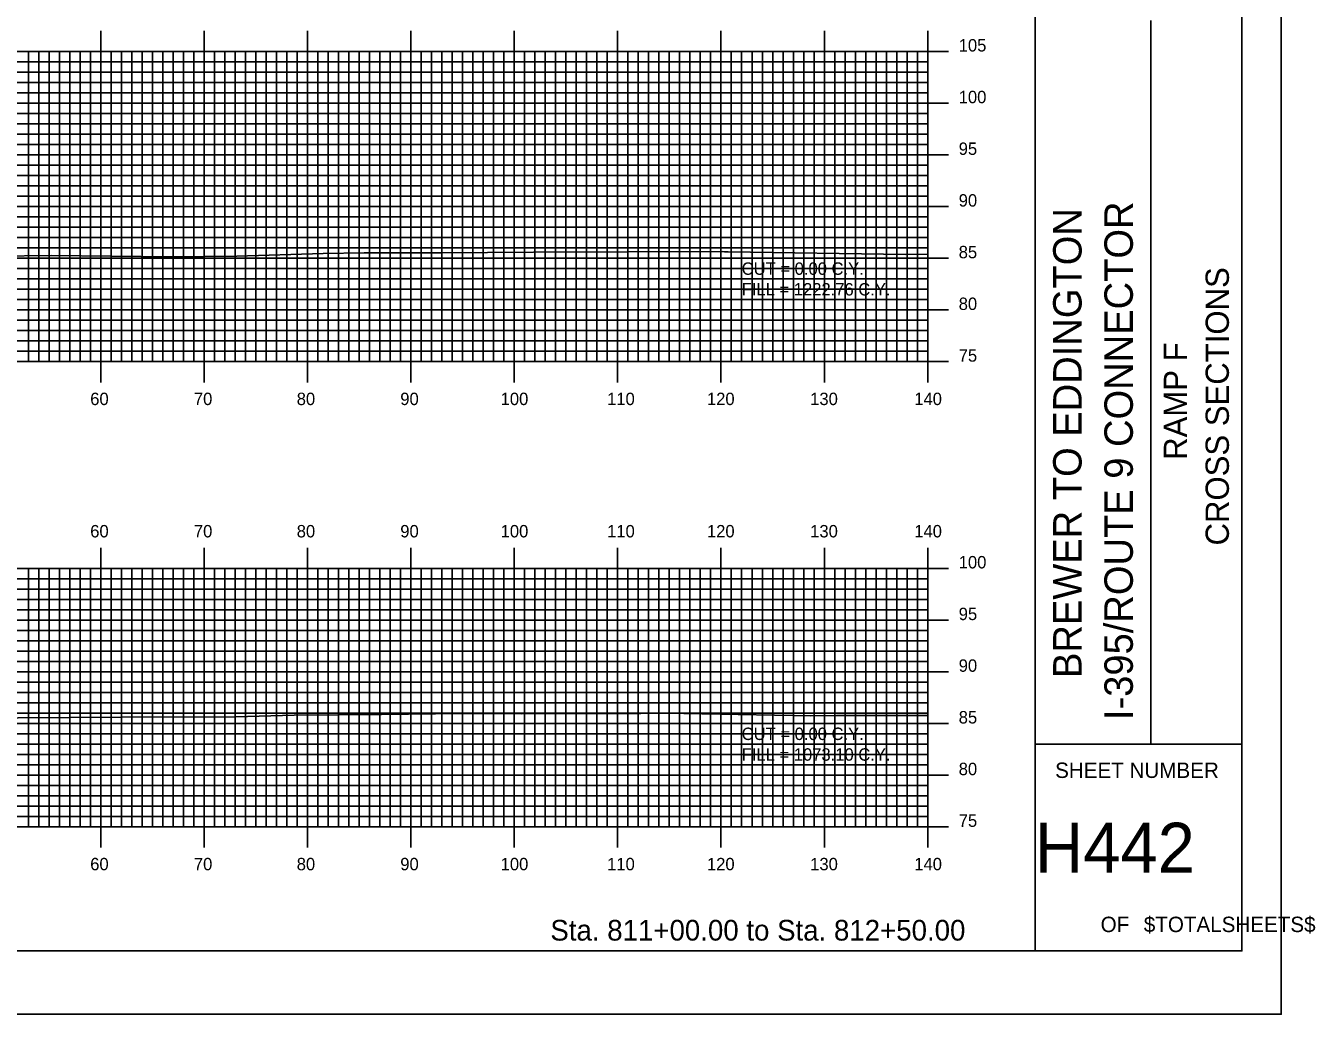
# Model space of a CAD drawing. Extents: x 2059 to 2403, y -1658 to -1438.
# Drawn here: x 2277.9 to 2402.7, y -1657.7 to -1562.1 of the extents above; entities that cross this region are included whole.
import ezdxf

# ---------------------------------------------------------------- set-up
doc = ezdxf.new("R2010")
doc.units = 0
for name, color, linetype in [('BORDER', 7, 'Continuous'), ('D_Text_Standard', 7, 'Continuous'), ('H_V ANNOTATION', 7, 'Continuous'), ('MAJOR', 7, 'Continuous'), ('MINOR', 7, 'Continuous'), ('PLOT BOUNDARY', 7, 'Continuous'), ('S_Roadway_Centerline', 7, 'Continuous')]:
    doc.layers.add(name, color=color, linetype=linetype)

msp = doc.modelspace()

# ---------------------------------------------------------------- linework, layer by layer
at = {"layer": 'BORDER'}
for p, q in [((2375.59, -1651.6), (2375.59, -1441.6)), ((2386.77, -1631.6), (2386.77, -1561.6)), ((2375.59, -1631.6), (2395.59, -1631.6))]:
    msp.add_line(p, q, dxfattribs=at)
msp.add_lwpolyline([(2075.59, -1651.6), (2395.59, -1651.6), (2395.59, -1441.6), (2075.59, -1441.6)], close=True, dxfattribs=at)
at = {"layer": 'MAJOR'}
for p, q in [((2285.19, -1562.6), (2285.19, -1564.6)), ((2295.19, -1562.6), (2295.19, -1564.6)), ((2305.19, -1562.6), (2305.19, -1564.6)), ((2315.19, -1562.6), (2315.19, -1564.6)), ((2325.19, -1562.6), (2325.19, -1564.6)), ((2335.19, -1562.6), (2335.19, -1564.6)), ((2345.19, -1562.6), (2345.19, -1564.6)), ((2355.19, -1562.6), (2355.19, -1564.6)), ((2365.19, -1562.6), (2365.19, -1564.6)), ((2085.19, -1564.6), (2365.19, -1564.6)), ((2085.19, -1564.6), (2365.19, -1564.6)), ((2285.19, -1594.6), (2285.19, -1564.6)), ((2295.19, -1594.6), (2295.19, -1564.6)), ((2305.19, -1594.6), (2305.19, -1564.6)), ((2315.19, -1594.6), (2315.19, -1564.6)), ((2325.19, -1594.6), (2325.19, -1564.6)), ((2335.19, -1594.6), (2335.19, -1564.6)), ((2345.19, -1594.6), (2345.19, -1564.6)), ((2355.19, -1594.6), (2355.19, -1564.6)), ((2367.19, -1564.6), (2363.18, -1564.6)), ((2365.19, -1594.6), (2365.19, -1564.6)), ((2365.19, -1594.6), (2365.19, -1564.6)), ((2085.19, -1569.6), (2365.19, -1569.6)), ((2367.19, -1569.6), (2363.18, -1569.6)), ((2085.19, -1574.6), (2365.19, -1574.6)), ((2367.19, -1574.6), (2363.18, -1574.6)), ((2085.19, -1579.6), (2365.19, -1579.6)), ((2367.19, -1579.6), (2363.18, -1579.6)), ((2085.19, -1584.6), (2365.19, -1584.6)), ((2367.19, -1584.6), (2363.18, -1584.6)), ((2085.19, -1589.6), (2365.19, -1589.6)), ((2367.19, -1589.6), (2363.18, -1589.6)), ((2085.19, -1594.6), (2365.19, -1594.6)), ((2085.19, -1594.6), (2365.19, -1594.6)), ((2285.19, -1596.61), (2285.19, -1594.6)), ((2295.19, -1596.61), (2295.19, -1594.6)), ((2305.19, -1596.61), (2305.19, -1594.6)), ((2315.19, -1596.61), (2315.19, -1594.6)), ((2325.19, -1596.61), (2325.19, -1594.6)), ((2335.19, -1596.61), (2335.19, -1594.6)), ((2345.19, -1596.61), (2345.19, -1594.6)), ((2355.19, -1596.61), (2355.19, -1594.6)), ((2367.19, -1594.6), (2363.18, -1594.6)), ((2365.19, -1596.61), (2365.19, -1594.6)), ((2285.19, -1612.6), (2285.19, -1614.6)), ((2295.19, -1612.6), (2295.19, -1614.6)), ((2305.19, -1612.6), (2305.19, -1614.6)), ((2315.19, -1612.6), (2315.19, -1614.6)), ((2325.19, -1612.6), (2325.19, -1614.6)), ((2335.19, -1612.6), (2335.19, -1614.6)), ((2345.19, -1612.6), (2345.19, -1614.6)), ((2355.19, -1612.6), (2355.19, -1614.6)), ((2365.19, -1612.6), (2365.19, -1614.6)), ((2085.19, -1614.6), (2365.19, -1614.6)), ((2085.19, -1614.6), (2365.19, -1614.6)), ((2285.19, -1639.6), (2285.19, -1614.6)), ((2295.19, -1639.6), (2295.19, -1614.6)), ((2305.19, -1639.6), (2305.19, -1614.6)), ((2315.19, -1639.6), (2315.19, -1614.6)), ((2325.19, -1639.6), (2325.19, -1614.6)), ((2335.19, -1639.6), (2335.19, -1614.6)), ((2345.19, -1639.6), (2345.19, -1614.6)), ((2355.19, -1639.6), (2355.19, -1614.6)), ((2367.19, -1614.6), (2363.18, -1614.6)), ((2365.19, -1639.6), (2365.19, -1614.6)), ((2365.19, -1639.6), (2365.19, -1614.6)), ((2085.19, -1619.6), (2365.19, -1619.6)), ((2367.19, -1619.6), (2363.18, -1619.6)), ((2085.19, -1624.6), (2365.19, -1624.6)), ((2367.19, -1624.6), (2363.18, -1624.6)), ((2085.19, -1629.6), (2365.19, -1629.6)), ((2367.19, -1629.6), (2363.18, -1629.6)), ((2085.19, -1634.6), (2365.19, -1634.6)), ((2367.19, -1634.6), (2363.18, -1634.6)), ((2085.19, -1639.6), (2365.19, -1639.6)), ((2085.19, -1639.6), (2365.19, -1639.6)), ((2285.19, -1641.61), (2285.19, -1639.6)), ((2295.19, -1641.61), (2295.19, -1639.6)), ((2305.19, -1641.61), (2305.19, -1639.6)), ((2315.19, -1641.61), (2315.19, -1639.6)), ((2325.19, -1641.61), (2325.19, -1639.6)), ((2335.19, -1641.61), (2335.19, -1639.6)), ((2345.19, -1641.61), (2345.19, -1639.6)), ((2355.19, -1641.61), (2355.19, -1639.6)), ((2367.19, -1639.6), (2363.18, -1639.6)), ((2365.19, -1641.61), (2365.19, -1639.6))]:
    msp.add_line(p, q, dxfattribs=at)
at = {"layer": 'MINOR'}
for p, q in [((2085.19, -1565.6), (2365.19, -1565.6)), ((2278.19, -1594.6), (2278.19, -1564.6)), ((2279.19, -1594.6), (2279.19, -1564.6)), ((2280.19, -1594.6), (2280.19, -1564.6)), ((2281.19, -1594.6), (2281.19, -1564.6)), ((2282.19, -1594.6), (2282.19, -1564.6)), ((2283.19, -1594.6), (2283.19, -1564.6)), ((2284.19, -1594.6), (2284.19, -1564.6)), ((2286.19, -1594.6), (2286.19, -1564.6)), ((2287.19, -1594.6), (2287.19, -1564.6)), ((2288.19, -1594.6), (2288.19, -1564.6)), ((2289.19, -1594.6), (2289.19, -1564.6)), ((2290.19, -1594.6), (2290.19, -1564.6)), ((2291.19, -1594.6), (2291.19, -1564.6)), ((2292.19, -1594.6), (2292.19, -1564.6)), ((2293.19, -1594.6), (2293.19, -1564.6)), ((2294.19, -1594.6), (2294.19, -1564.6)), ((2296.19, -1594.6), (2296.19, -1564.6)), ((2297.19, -1594.6), (2297.19, -1564.6)), ((2298.19, -1594.6), (2298.19, -1564.6)), ((2299.19, -1594.6), (2299.19, -1564.6)), ((2300.19, -1594.6), (2300.19, -1564.6)), ((2301.19, -1594.6), (2301.19, -1564.6)), ((2302.19, -1594.6), (2302.19, -1564.6)), ((2303.19, -1594.6), (2303.19, -1564.6)), ((2304.19, -1594.6), (2304.19, -1564.6)), ((2306.19, -1594.6), (2306.19, -1564.6)), ((2307.19, -1594.6), (2307.19, -1564.6)), ((2308.19, -1594.6), (2308.19, -1564.6)), ((2309.19, -1594.6), (2309.19, -1564.6)), ((2310.19, -1594.6), (2310.19, -1564.6)), ((2311.19, -1594.6), (2311.19, -1564.6)), ((2312.19, -1594.6), (2312.19, -1564.6)), ((2313.19, -1594.6), (2313.19, -1564.6)), ((2314.19, -1594.6), (2314.19, -1564.6)), ((2316.19, -1594.6), (2316.19, -1564.6)), ((2317.19, -1594.6), (2317.19, -1564.6)), ((2318.19, -1594.6), (2318.19, -1564.6)), ((2319.19, -1594.6), (2319.19, -1564.6)), ((2320.19, -1594.6), (2320.19, -1564.6)), ((2321.19, -1594.6), (2321.19, -1564.6)), ((2322.19, -1594.6), (2322.19, -1564.6)), ((2323.19, -1594.6), (2323.19, -1564.6)), ((2324.19, -1594.6), (2324.19, -1564.6)), ((2326.19, -1594.6), (2326.19, -1564.6)), ((2327.19, -1594.6), (2327.19, -1564.6)), ((2328.19, -1594.6), (2328.19, -1564.6)), ((2329.19, -1594.6), (2329.19, -1564.6)), ((2330.19, -1594.6), (2330.19, -1564.6)), ((2331.19, -1594.6), (2331.19, -1564.6)), ((2332.19, -1594.6), (2332.19, -1564.6)), ((2333.19, -1594.6), (2333.19, -1564.6)), ((2334.19, -1594.6), (2334.19, -1564.6)), ((2336.19, -1594.6), (2336.19, -1564.6)), ((2337.19, -1594.6), (2337.19, -1564.6)), ((2338.19, -1594.6), (2338.19, -1564.6)), ((2339.19, -1594.6), (2339.19, -1564.6)), ((2340.19, -1594.6), (2340.19, -1564.6)), ((2341.19, -1594.6), (2341.19, -1564.6)), ((2342.19, -1594.6), (2342.19, -1564.6)), ((2343.19, -1594.6), (2343.19, -1564.6)), ((2344.19, -1594.6), (2344.19, -1564.6)), ((2346.19, -1594.6), (2346.19, -1564.6)), ((2347.19, -1594.6), (2347.19, -1564.6)), ((2348.19, -1594.6), (2348.19, -1564.6)), ((2349.19, -1594.6), (2349.19, -1564.6)), ((2350.19, -1594.6), (2350.19, -1564.6)), ((2351.19, -1594.6), (2351.19, -1564.6)), ((2352.19, -1594.6), (2352.19, -1564.6)), ((2353.19, -1594.6), (2353.19, -1564.6)), ((2354.19, -1594.6), (2354.19, -1564.6)), ((2356.19, -1594.6), (2356.19, -1564.6)), ((2357.19, -1594.6), (2357.19, -1564.6)), ((2358.19, -1594.6), (2358.19, -1564.6)), ((2359.19, -1594.6), (2359.19, -1564.6)), ((2360.19, -1594.6), (2360.19, -1564.6)), ((2361.19, -1594.6), (2361.19, -1564.6)), ((2362.19, -1594.6), (2362.19, -1564.6)), ((2365.19, -1565.6), (2363.18, -1565.6)), ((2363.19, -1594.6), (2363.19, -1564.6)), ((2364.19, -1594.6), (2364.19, -1564.6)), ((2085.19, -1566.6), (2365.19, -1566.6)), ((2365.19, -1566.6), (2363.18, -1566.6)), ((2085.19, -1567.6), (2365.19, -1567.6)), ((2365.19, -1567.6), (2363.18, -1567.6)), ((2085.19, -1568.6), (2365.19, -1568.6)), ((2365.19, -1568.6), (2363.18, -1568.6)), ((2085.19, -1570.6), (2365.19, -1570.6)), ((2365.19, -1570.6), (2363.18, -1570.6)), ((2085.19, -1571.6), (2365.19, -1571.6)), ((2365.19, -1571.6), (2363.18, -1571.6)), ((2085.19, -1572.6), (2365.19, -1572.6)), ((2365.19, -1572.6), (2363.18, -1572.6)), ((2085.19, -1573.6), (2365.19, -1573.6)), ((2365.19, -1573.6), (2363.18, -1573.6)), ((2085.19, -1575.6), (2365.19, -1575.6)), ((2365.19, -1575.6), (2363.18, -1575.6)), ((2085.19, -1576.6), (2365.19, -1576.6)), ((2365.19, -1576.6), (2363.18, -1576.6)), ((2085.19, -1577.6), (2365.19, -1577.6)), ((2365.19, -1577.6), (2363.18, -1577.6)), ((2085.19, -1578.6), (2365.19, -1578.6)), ((2365.19, -1578.6), (2363.18, -1578.6)), ((2085.19, -1580.6), (2365.19, -1580.6)), ((2365.19, -1580.6), (2363.18, -1580.6)), ((2085.19, -1581.6), (2365.19, -1581.6)), ((2365.19, -1581.6), (2363.18, -1581.6)), ((2085.19, -1582.6), (2365.19, -1582.6)), ((2365.19, -1582.6), (2363.18, -1582.6)), ((2085.19, -1583.6), (2365.19, -1583.6)), ((2365.19, -1583.6), (2363.18, -1583.6)), ((2085.19, -1585.6), (2365.19, -1585.6)), ((2365.19, -1585.6), (2363.18, -1585.6)), ((2085.19, -1586.6), (2365.19, -1586.6)), ((2365.19, -1586.6), (2363.18, -1586.6)), ((2085.19, -1587.6), (2365.19, -1587.6)), ((2365.19, -1587.6), (2363.18, -1587.6)), ((2085.19, -1588.6), (2365.19, -1588.6)), ((2365.19, -1588.6), (2363.18, -1588.6)), ((2085.19, -1590.6), (2365.19, -1590.6)), ((2365.19, -1590.6), (2363.18, -1590.6)), ((2085.19, -1591.6), (2365.19, -1591.6)), ((2365.19, -1591.6), (2363.18, -1591.6)), ((2085.19, -1592.6), (2365.19, -1592.6)), ((2365.19, -1592.6), (2363.18, -1592.6)), ((2085.19, -1593.6), (2365.19, -1593.6)), ((2365.19, -1593.6), (2363.18, -1593.6)), ((2278.19, -1639.6), (2278.19, -1614.6)), ((2279.19, -1639.6), (2279.19, -1614.6)), ((2280.19, -1639.6), (2280.19, -1614.6)), ((2281.19, -1639.6), (2281.19, -1614.6)), ((2282.19, -1639.6), (2282.19, -1614.6)), ((2283.19, -1639.6), (2283.19, -1614.6)), ((2284.19, -1639.6), (2284.19, -1614.6)), ((2286.19, -1639.6), (2286.19, -1614.6)), ((2287.19, -1639.6), (2287.19, -1614.6)), ((2288.19, -1639.6), (2288.19, -1614.6)), ((2289.19, -1639.6), (2289.19, -1614.6)), ((2290.19, -1639.6), (2290.19, -1614.6)), ((2291.19, -1639.6), (2291.19, -1614.6)), ((2292.19, -1639.6), (2292.19, -1614.6)), ((2293.19, -1639.6), (2293.19, -1614.6)), ((2294.19, -1639.6), (2294.19, -1614.6)), ((2296.19, -1639.6), (2296.19, -1614.6)), ((2297.19, -1639.6), (2297.19, -1614.6)), ((2298.19, -1639.6), (2298.19, -1614.6)), ((2299.19, -1639.6), (2299.19, -1614.6)), ((2300.19, -1639.6), (2300.19, -1614.6)), ((2301.19, -1639.6), (2301.19, -1614.6)), ((2302.19, -1639.6), (2302.19, -1614.6)), ((2303.19, -1639.6), (2303.19, -1614.6)), ((2304.19, -1639.6), (2304.19, -1614.6)), ((2306.19, -1639.6), (2306.19, -1614.6)), ((2307.19, -1639.6), (2307.19, -1614.6)), ((2308.19, -1639.6), (2308.19, -1614.6)), ((2309.19, -1639.6), (2309.19, -1614.6)), ((2310.19, -1639.6), (2310.19, -1614.6)), ((2311.19, -1639.6), (2311.19, -1614.6)), ((2312.19, -1639.6), (2312.19, -1614.6)), ((2313.19, -1639.6), (2313.19, -1614.6)), ((2314.19, -1639.6), (2314.19, -1614.6)), ((2316.19, -1639.6), (2316.19, -1614.6)), ((2317.19, -1639.6), (2317.19, -1614.6)), ((2318.19, -1639.6), (2318.19, -1614.6)), ((2319.19, -1639.6), (2319.19, -1614.6)), ((2320.19, -1639.6), (2320.19, -1614.6)), ((2321.19, -1639.6), (2321.19, -1614.6)), ((2322.19, -1639.6), (2322.19, -1614.6)), ((2323.19, -1639.6), (2323.19, -1614.6)), ((2324.19, -1639.6), (2324.19, -1614.6)), ((2326.19, -1639.6), (2326.19, -1614.6)), ((2327.19, -1639.6), (2327.19, -1614.6)), ((2328.19, -1639.6), (2328.19, -1614.6)), ((2329.19, -1639.6), (2329.19, -1614.6)), ((2330.19, -1639.6), (2330.19, -1614.6)), ((2331.19, -1639.6), (2331.19, -1614.6)), ((2332.19, -1639.6), (2332.19, -1614.6)), ((2333.19, -1639.6), (2333.19, -1614.6)), ((2334.19, -1639.6), (2334.19, -1614.6)), ((2336.19, -1639.6), (2336.19, -1614.6)), ((2337.19, -1639.6), (2337.19, -1614.6)), ((2338.19, -1639.6), (2338.19, -1614.6)), ((2339.19, -1639.6), (2339.19, -1614.6)), ((2340.19, -1639.6), (2340.19, -1614.6)), ((2341.19, -1639.6), (2341.19, -1614.6)), ((2342.19, -1639.6), (2342.19, -1614.6)), ((2343.19, -1639.6), (2343.19, -1614.6)), ((2344.19, -1639.6), (2344.19, -1614.6)), ((2346.19, -1639.6), (2346.19, -1614.6)), ((2347.19, -1639.6), (2347.19, -1614.6)), ((2348.19, -1639.6), (2348.19, -1614.6)), ((2349.19, -1639.6), (2349.19, -1614.6)), ((2350.19, -1639.6), (2350.19, -1614.6)), ((2351.19, -1639.6), (2351.19, -1614.6)), ((2352.19, -1639.6), (2352.19, -1614.6)), ((2353.19, -1639.6), (2353.19, -1614.6)), ((2354.19, -1639.6), (2354.19, -1614.6)), ((2356.19, -1639.6), (2356.19, -1614.6)), ((2357.19, -1639.6), (2357.19, -1614.6)), ((2358.19, -1639.6), (2358.19, -1614.6)), ((2359.19, -1639.6), (2359.19, -1614.6)), ((2360.19, -1639.6), (2360.19, -1614.6)), ((2361.19, -1639.6), (2361.19, -1614.6)), ((2362.19, -1639.6), (2362.19, -1614.6)), ((2363.19, -1639.6), (2363.19, -1614.6)), ((2364.19, -1639.6), (2364.19, -1614.6)), ((2085.19, -1615.6), (2365.19, -1615.6)), ((2085.19, -1616.6), (2365.19, -1616.6)), ((2365.19, -1615.6), (2363.18, -1615.6)), ((2365.19, -1616.6), (2363.18, -1616.6)), ((2085.19, -1617.6), (2365.19, -1617.6)), ((2365.19, -1617.6), (2363.18, -1617.6)), ((2085.19, -1618.6), (2365.19, -1618.6)), ((2365.19, -1618.6), (2363.18, -1618.6)), ((2085.19, -1620.6), (2365.19, -1620.6)), ((2085.19, -1621.6), (2365.19, -1621.6)), ((2365.19, -1620.6), (2363.18, -1620.6)), ((2365.19, -1621.6), (2363.18, -1621.6)), ((2085.19, -1622.6), (2365.19, -1622.6)), ((2365.19, -1622.6), (2363.18, -1622.6)), ((2085.19, -1623.6), (2365.19, -1623.6)), ((2365.19, -1623.6), (2363.18, -1623.6)), ((2085.19, -1625.6), (2365.19, -1625.6)), ((2085.19, -1626.6), (2365.19, -1626.6)), ((2365.19, -1625.6), (2363.18, -1625.6)), ((2365.19, -1626.6), (2363.18, -1626.6)), ((2085.19, -1627.6), (2365.19, -1627.6)), ((2365.19, -1627.6), (2363.18, -1627.6)), ((2085.19, -1628.6), (2365.19, -1628.6)), ((2365.19, -1628.6), (2363.18, -1628.6)), ((2085.19, -1630.6), (2365.19, -1630.6)), ((2085.19, -1631.6), (2365.19, -1631.6)), ((2365.19, -1630.6), (2363.18, -1630.6)), ((2365.19, -1631.6), (2363.18, -1631.6)), ((2085.19, -1632.6), (2365.19, -1632.6)), ((2365.19, -1632.6), (2363.18, -1632.6)), ((2085.19, -1633.6), (2365.19, -1633.6)), ((2365.19, -1633.6), (2363.18, -1633.6)), ((2085.19, -1635.6), (2365.19, -1635.6)), ((2085.19, -1636.6), (2365.19, -1636.6)), ((2365.19, -1635.6), (2363.18, -1635.6)), ((2365.19, -1636.6), (2363.18, -1636.6)), ((2085.19, -1637.6), (2365.19, -1637.6)), ((2365.19, -1637.6), (2363.18, -1637.6)), ((2085.19, -1638.6), (2365.19, -1638.6)), ((2365.19, -1638.6), (2363.18, -1638.6))]:
    msp.add_line(p, q, dxfattribs=at)
at = {"layer": 'PLOT BOUNDARY'}
msp.add_lwpolyline([(2059.4, -1657.72), (2399.4, -1657.72), (2399.4, -1437.72), (2059.4, -1437.72)], close=True, dxfattribs=at)
at = {"layer": 'S_Roadway_Centerline'}
for points in [[(2275.14, -1584.38), (2280.43, -1584.34), (2291.95, -1584.46), (2298.34, -1584.38), (2306.71, -1584.13), (2310.65, -1584.06), (2318.14, -1584.06), (2327.06, -1584), (2345.34, -1583.96), (2345.54, -1583.97), (2345.63, -1583.97), (2345.89, -1583.97), (2363.06, -1584.23), (2365.19, -1584.2)], [(2272.13, -1629.07), (2287.23, -1628.99), (2298.25, -1628.95), (2303.88, -1628.81), (2312.35, -1628.73), (2320.19, -1628.65), (2325.87, -1628.68), (2337.43, -1628.63), (2339.82, -1628.61), (2353.87, -1628.85), (2356.38, -1628.84), (2365.19, -1628.83)]]:
    msp.add_lwpolyline(points, dxfattribs=at)

# ---------------------------------------------------------------- texts
at = {"layer": 'BORDER'}
for s, height, p in [('I-395/ROUTE 9 CONNECTOR', 2.7557, (2385.04, -1629.27)), ('BREWER TO EDDINGTON', 2.7557, (2380.08, -1625.2)), ('CROSS SECTIONS', 2.25, (2394.33, -1612.38)), ('RAMP F', 2.25, (2390.28, -1604.1))]:
    msp.add_text(s, height=height, rotation=90, dxfattribs=at).set_placement(p)
for s, height, p in [('SHEET NUMBER', 1.4905, (2377.52, -1634.87)), ('H442', 4.839, (2375.57, -1644.04)), ('OF', 1.491, (2381.92, -1649.78)), ('$TOTALSHEETS$', 1.4905, (2386.1, -1649.78))]:
    msp.add_text(s, height=height, dxfattribs=at).set_placement(p)
at = {"layer": 'D_Text_Standard'}
for s, p in [('CUT = 0.00 C.Y.', (2347.19, -1586.2)), ('FILL = 1222.76 C.Y.', (2347.19, -1588.2)), ('CUT = 0.00 C.Y.', (2347.19, -1631.2)), ('FILL = 1073.10 C.Y.', (2347.19, -1633.2))]:
    msp.add_text(s, height=1.2, dxfattribs=at).set_placement(p)
at = {"layer": 'H_V ANNOTATION'}
for s, height, p in [('105', 1.2, (2368.19, -1564.6)), ('100', 1.2, (2368.19, -1569.6)), ('95', 1.2, (2368.19, -1574.6)), ('90', 1.2, (2368.19, -1579.6)), ('85', 1.2, (2368.19, -1584.6)), ('80', 1.2, (2368.19, -1589.6)), ('75', 1.2, (2368.19, -1594.6)), ('60', 1.2, (2284.16, -1598.8)), ('70', 1.2, (2294.19, -1598.8)), ('80', 1.2, (2304.14, -1598.8)), ('90', 1.2, (2314.16, -1598.8)), ('100', 1.2, (2323.87, -1598.8)), ('110', 1.2, (2334.17, -1598.8)), ('120', 1.2, (2343.83, -1598.8)), ('130', 1.2, (2353.82, -1598.8)), ('140', 1.2, (2363.89, -1598.8)), ('60', 1.2, (2284.16, -1611.6)), ('70', 1.2, (2294.19, -1611.6)), ('80', 1.2, (2304.14, -1611.6)), ('90', 1.2, (2314.16, -1611.6)), ('100', 1.2, (2323.87, -1611.6)), ('110', 1.2, (2334.17, -1611.6)), ('120', 1.2, (2343.83, -1611.6)), ('130', 1.2, (2353.82, -1611.6)), ('140', 1.2, (2363.89, -1611.6)), ('100', 1.2, (2368.19, -1614.6)), ('95', 1.2, (2368.19, -1619.6)), ('90', 1.2, (2368.19, -1624.6)), ('85', 1.2, (2368.19, -1629.6)), ('80', 1.2, (2368.19, -1634.6)), ('75', 1.2, (2368.19, -1639.6)), ('60', 1.2, (2284.16, -1643.8)), ('70', 1.2, (2294.19, -1643.8)), ('80', 1.2, (2304.14, -1643.8)), ('90', 1.2, (2314.16, -1643.8)), ('100', 1.2, (2323.87, -1643.8)), ('110', 1.2, (2334.17, -1643.8)), ('120', 1.2, (2343.83, -1643.8)), ('130', 1.2, (2353.82, -1643.8)), ('140', 1.2, (2363.89, -1643.8)), ('Sta. 811+00.00 to Sta. 812+50.00', 2.0004, (2328.68, -1650.6))]:
    msp.add_text(s, height=height, dxfattribs=at).set_placement(p)

doc.saveas('drawing.dxf')
